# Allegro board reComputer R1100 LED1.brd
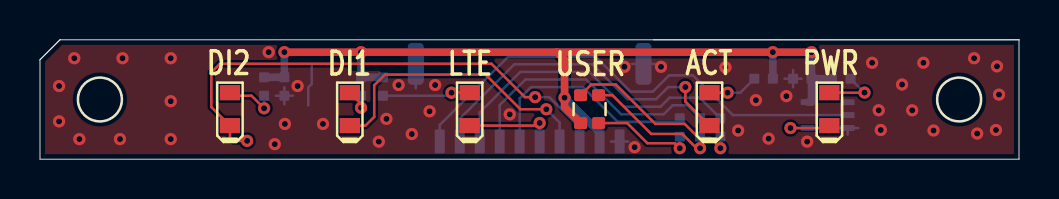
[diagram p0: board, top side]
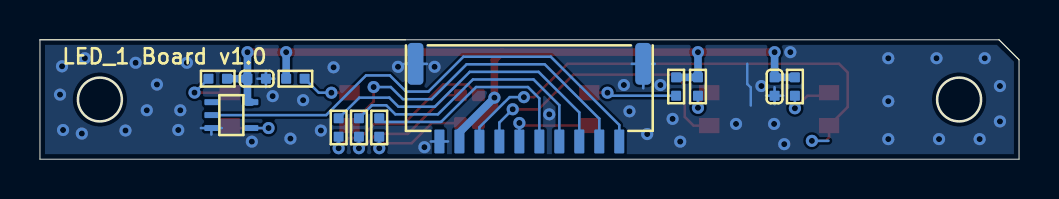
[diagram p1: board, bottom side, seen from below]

Outline 49 x 6 mm; copper layers: TOP, BOTTOM. Coordinates in mm from the lower left corner of the outline.
Outline path: circle c3,3 r1.1 ; circle c3,3 r1.1 ; circle c46,3 r1.1 ; circle c46,3 r1.1 ; 0,5 0,0 49,0 49,6 ; 0,5 1,6 ; 0,5 1,6 ; 1,6 49,6 ; 49,6 30.7,6

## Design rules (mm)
constraint set DEFAULT: min track width 0.127

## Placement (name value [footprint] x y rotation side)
J1  1.0-10A-WT  [JST10_2P_1D0_12_35X4_3X3_2MM]  24.51 0.89 0 bottom
LC2  1uF  [C0402]  38.15 4.05 0 bottom
LC3  1uF  [C0402]  12.23 3.65 90 bottom
LED1  Emerald Green  [LED0603]  39.51 2.51 90 top
LED4  Emerald Green  [LED0603]  33.51 2.51 90 top
LED5  Emerald Green  [LED0603]  21.51 2.51 90 top
LED6  Emerald Green  [LED0603]  15.51 2.51 90 top
LED7  Emerald Green  [LED0603]  9.51 2.51 90 top
LED9  RGB  [LED_4P_1_6X1_6MM_RGB]  27.51 2.51 270 top
LR2  51R  [R0402]  17.16 3.65 270 bottom
LR5  51R  [R0402]  40.1 4.05 0 bottom
LR6  51R  [R0402]  36.22 4.05 180 bottom
LR7  51R  [R0402]  16.07 3.65 270 bottom
LR10  51R  [R0402]  11.22 3.65 270 bottom
LR13  51R  [R0402]  34.05 1.59 90 bottom
LR14  51R  [R0402]  33.04 1.59 90 bottom
LR15  51R  [R0402]  32.02 1.59 90 bottom
U1  74LVC1G07GW  [SOT353]  39.42 2.22 270 bottom

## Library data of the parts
J1 = JST_10+2P
LC2 LC3 = CC
LED1 LED4-LED7 = Single LED
LED9 = RGB_LED_19-237
LR2 LR5-LR7 LR10 LR13-LR15 = R
U1 = SN74LVC1G07DCK

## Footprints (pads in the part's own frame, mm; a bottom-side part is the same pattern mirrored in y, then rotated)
C0402
  rrect 0.5x0.5 smd: 1(-0.463,0) 2(0.463,0)
JST10_2P_1D0_12_35X4_3X3_2MM
  rrect 0.5x1.2 smd: 1(-4.5,0) 2(-3.5,0) 3(-2.5,0) 4(-1.5,0) 5(-0.5,0) 6(0.5,0) 7(1.5,0) 8(2.5,0) 9(3.5,0) 10(4.5,0)
  rrect 0.8x2.1 smd: S1(-5.7,-3.9) S2(5.7,-3.9)
LED0603
  rect 0.762x1.016 smd: 1(0.826,0) 2(-0.826,0)
LED_4P_1_6X1_6MM_RGB
  rrect 0.6x0.65 smd: 1(-0.7,-0.45) 2(0.7,-0.45) 3(-0.7,0.45) 4(0.7,0.45)
R0402
  rrect 0.5x0.5 smd: 1(-0.463,0) 2(0.463,0)
SOT353
  rrect 0.3x0.7 smd: 1(-0.65,-1) 2(0,-1) 3(0.65,-1) 4(0.65,1) 5(-0.65,1)

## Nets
GND: J1.10 J1.S1 J1.S2 LC2.1 LC3.1 U1.3
VDD_3V3_SYS: J1.9 LC2.2 LC3.2 LED9.2 LR2.1 LR5.1 LR6.1 LR7.1 LR10.1 U1.5
CM4_IN1_LED: J1.7 LED6.2(C)
CM4_IN2_LED: J1.8 LED7.2(C)
LTE_LED_WWAN#: J1.6 LED5.2(C)
NPWR_LED: J1.1 U1.2
PL_NLED: J1.2 LED4.2(C)
USER_LED_B: J1.5 LR15.2
USER_LED_G: J1.4 LR14.2
USER_LED_R: J1.3 LR13.2
N19185: LED1.1 LR5.2
N19189: LED4.1 LR6.2
N19259: LED1.2(C) U1.4(Y)
N35488: LED9.1(RED) LR13.1
N35492: LED9.3 LR14.1
N35496: LED9.4 LR15.1
N330391: LED5.1 LR2.2
N331441: LED6.1 LR7.2
N332491: LED7.1 LR10.2

Pads without a net: U1 1

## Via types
v1: diameter 0.61, hole 0.305, TOP to BOTTOM, 61 vias

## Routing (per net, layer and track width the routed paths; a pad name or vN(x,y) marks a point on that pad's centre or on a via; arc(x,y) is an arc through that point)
GND: length 11.4
  BOTTOM w0.127: U1.3 40.95,1.57 ; U1.3 39.89,1.57 ; U1.3 40.42,1.24 ; LC2.1 38.12,4.05 ; LC2.1 37.26,4.05 ; LC2.1 37.69,3.62 ; LC2.1 37.69,4.47 ; 13.6,4.79 13.6,3.78 13.43,3.61 13.43,2.7 ; J1.S1 19.39,4.79 ; J1.S1 18.23,4.79 ; J1.S1 18.81,3.56 ; 11.8,3.19 LC3.1 ; LC3.1 12.23,2.76 ; LC3.1 12.23,3.62 ; LC3.1 12.66,3.19 ; 29.63,4.79 J1.S2 30.79,4.79 ; 28.58,0.89 J1.10 29.44,0.89
  vias: v1(0.96,3.68) v1(0.96,1.9) v1(1.72,5.07) v1(1.97,1.01) v1(4,1.01) v1(4.13,5.07) v1(6.54,5.07) v1(6.54,2.91) v1(6.54,1.01) v1(11.45,5.38) v1(11.75,0.76) v1(12.26,1.77) v1(12.89,3.68) v1(14.16,1.77) v1(16.96,0.88) v1(17.34,2.03) v1(17.95,3.73) v1(18.61,1.26) v1(19.5,2.41) v1(19.78,3.73) v1(23.51,2.25) v1(29.25,4.64) v1(29.76,0.6) v1(31.08,4.64) v1(34.31,4.62) v1(34.94,1.44) v1(35.83,2.97) v1(36.46,1.04) v1(37.35,3.17) v1(38.4,0.88) v1(41.65,4.85) v1(41.98,2.46) v1(42.08,1.47) v1(43.14,3.75) v1(43.65,2.46) v1(44.21,4.85) v1(44.72,1.44) v1(46.75,5.07) v1(46.9,1.29) v1(47.84,1.47) v1(47.89,4.67) v1(48,3.25)
VDD_3V3_SYS: length 43.1
  TOP w0.381: 25.87,5.38 v1(16.07,5.38) v1(12.23,5.38) ; 25.87,5.38 v1(36.68,5.38) v1(38.62,5.38) ; 25.87,5.38 26.25,5 v1(26.25,3.09) 26.25,2.62 LED9.2
  BOTTOM w0.381: LR6.1 v1(36.68,5.38) ; v1(26.25,3.09) 28.01,1.34 J1.9 ; LR10.1 LC3.2 v1(12.23,5.38) ; LC2.2 v1(38.62,5.38) ; LC2.2 LR5.1 ; LC2.2 38.62,2.87 U1.5 ; v1(16.07,5.38) LR7.1 LR2.1
CM4_IN1_LED: length 14.4
  TOP w0.127: LED6.2 16.29,1.69 16.73,2.13 16.73,3.72 17.26,4.25 22.3,4.25 24.04,2.51 v1(25.34,2.51)
  BOTTOM w0.127: J1.7 26.01,1.84 v1(25.34,2.51)
CM4_IN2_LED: length 26.1
  TOP w0.127: v1(24.78,3.12) 24.27,3.12 22.6,4.79 9.01,4.79 8.58,4.36 8.58,2.62 LED7.2 9.51,1.09 9.68,0.92 v1(10.37,0.92)
  BOTTOM w0.127: v1(24.78,3.12) 25.49,3.12 27.01,1.6 J1.8 ; 9.54,0.92 v1(10.37,0.92)
LTE_LED_WWAN#: length 4.5
  TOP w0.127: LED5.2 24.88,1.69 v1(25.01,1.82)
  BOTTOM w0.127: J1.6 v1(25.01,1.82)
NPWR_LED: length 24.6
  BOTTOM w0.127: U1.2 34.67,2.22 32.68,4.21 31.49,4.21 30.67,3.4 29.56,3.4 27.8,5.15 23.43,5.15 20.01,1.72 J1.1
PL_NLED: length 17
  TOP w0.127: v1(32.3,3.63) 32.3,2.9 LED4.2
  BOTTOM w0.127: J1.2 21.01,2.04 23.74,4.77 27.65,4.77 29.4,3.02 30.83,3.02 31.44,3.63 v1(32.3,3.63)
USER_LED_B: length 11.2
  BOTTOM w0.127: J1.5 24.01,3.06 24.58,3.63 27.17,3.63 28.92,1.87 31.84,1.87 LR15.2
USER_LED_G: length 13.6
  BOTTOM w0.127: LR14.2 32.38,2.71 31.67,2.71 31.21,2.25 29.08,2.25 27.33,4.01 24.3,4.01 23.01,2.72 J1.4
USER_LED_R: length 15.7
  BOTTOM w0.127: J1.3 22.01,2.35 24.04,4.39 27.49,4.39 29.24,2.64 31.05,2.64 31.51,3.09 33.02,3.09 LR13.2
N19185: length 2.8
  TOP w0.127: v1(41.27,3.35) 41.26,3.34 LED1.1
  BOTTOM w0.127: v1(41.26,3.35) LR5.2
N19189: length 2.5
  TOP w0.127: LED4.1 v1(34.41,3.34)
  BOTTOM w0.127: v1(34.41,3.34) 35.05,3.34 LR6.2
N19259: length 2.9
  TOP w0.127: v1(37.56,1.57) 39.38,1.57 LED1.2
  BOTTOM w0.127: U1.4 v1(37.56,1.57)
N35488: length 9.1
  TOP w0.127: v1(34.05,0.55) 33.54,1.06 32.98,1.06 32.27,1.77 30.8,1.77 28.82,3.75 27.6,3.75 LED9.1
  BOTTOM w0.127: LR13.1 v1(34.05,0.55)
N35492: length 6.8
  TOP w0.127: v1(33.04,0.55) 32.86,0.55 32.14,1.27 30.59,1.27 28.65,3.21 LED9.3
  BOTTOM w0.127: LR14.1 v1(33.04,0.55)
N35496: length 5.2
  TOP w0.127: v1(32.02,0.55) 31.77,0.8 30.4,0.8 29.39,1.81 LED9.4
  BOTTOM w0.127: LR15.1 v1(32.02,0.55)
N330391: length 4.4
  TOP w0.127: LED5.1 v1(20.6,3.34)
  BOTTOM w0.127: v1(20.6,3.34) 20.44,3.19 LR2.2
N331441: length 1.6
  TOP w0.127: v1(16.07,2.58) 16.07,2.78 LED6.1
  BOTTOM w0.127: LR7.2 v1(16.07,2.58)
N332491: length 2.7
  TOP w0.127: v1(11.22,2.56) 10.59,3.19 9.66,3.19 LED7.1
  BOTTOM w0.127: LR10.2 v1(11.22,2.56)

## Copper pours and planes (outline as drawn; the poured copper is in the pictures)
GND on TOP: 1.11,5.75 48.75,5.75 48.75,0.25 0.25,0.25 0.25,4.89 ; 3 cut-outs
GND on BOTTOM: 1.11,5.75 48.75,5.75 48.75,0.25 0.25,0.25 0.25,4.89 ; 6 cut-outs

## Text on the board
Ref Des/Silkscreen Bottom: LED_1 Board v1.0
Ref Des/Silkscreen Top: DI2 | DI1 | LTE | USER | ACT | PWR
User.22: FIGURE | FINISHED_SIZE | 12.0 | DRILL CHART: TOP to BOTTOM | ALL UNITS ARE IN MILS | PLATED | QTY | 61 | TOTAL HOLES:
